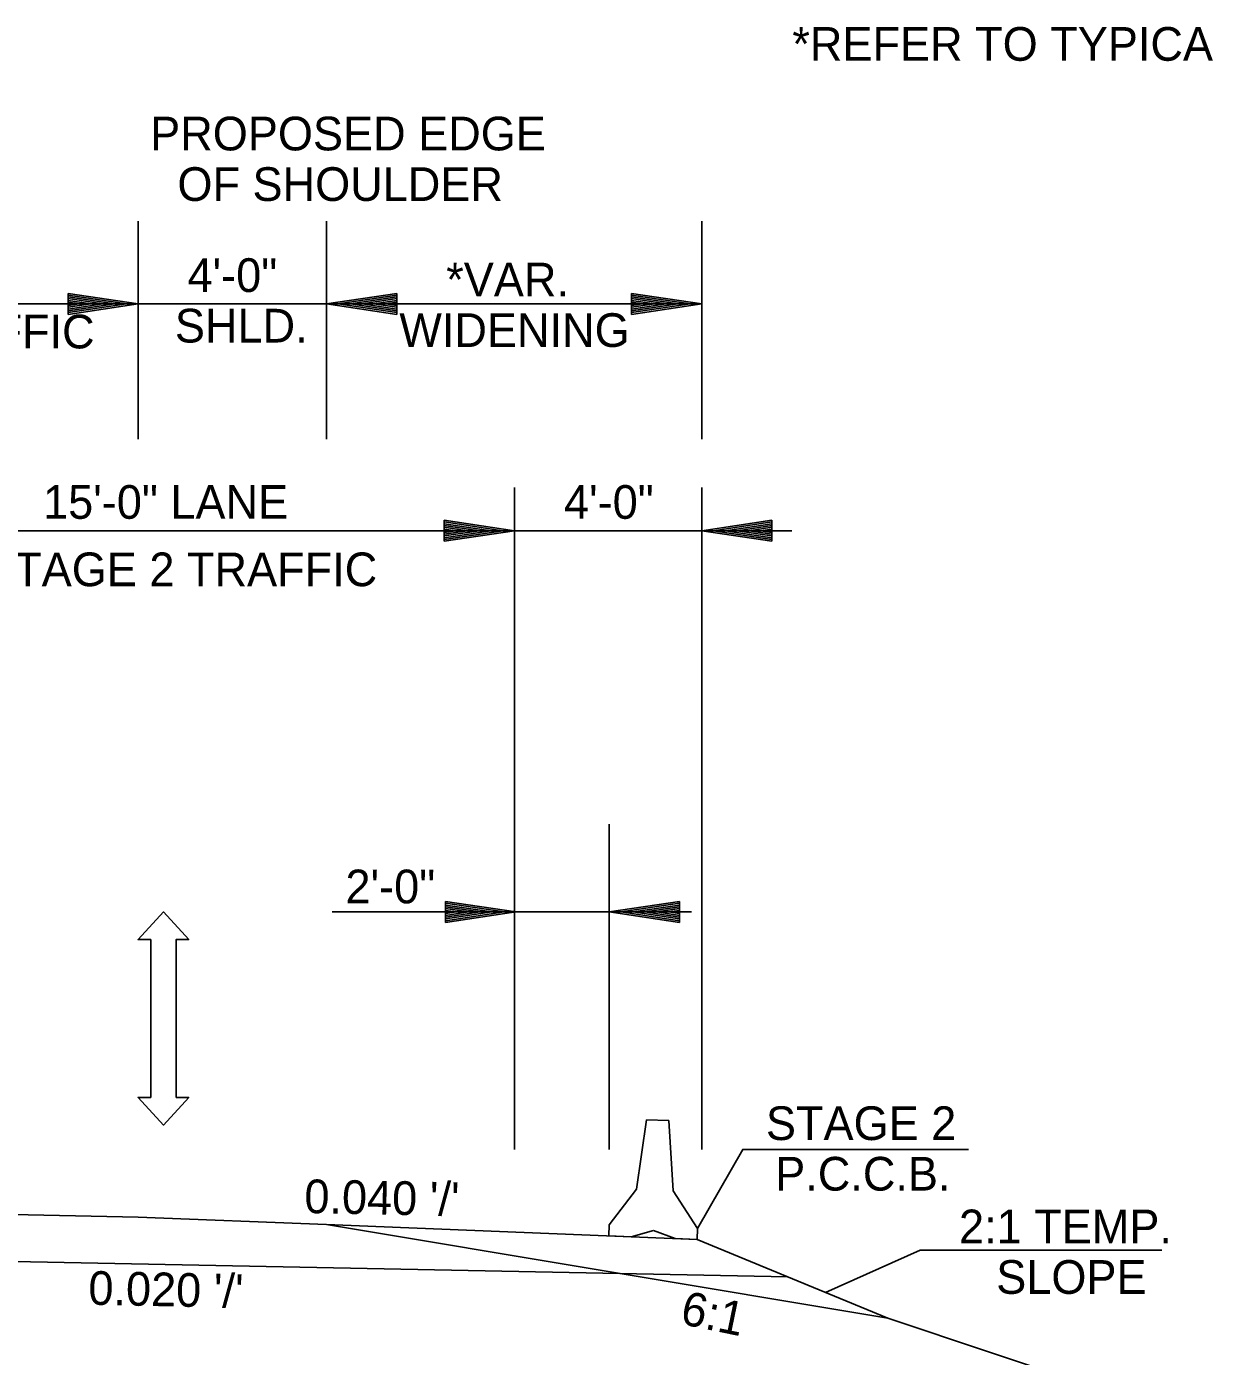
# Model space of a CAD drawing. Extents: x 1807779 to 1818251, y 673292 to 678849.
# Drawn here: x 1813573.8 to 1813826.1, y 678564.5 to 678848.6 of the extents above; entities that cross this region are included whole.
import ezdxf

# ---------------------------------------------------------------- set-up
doc = ezdxf.new("R2010")
doc.units = 0
for name, color, linetype in [('Dimensions', 7, 'Continuous'), ('EX_DRIVEWAY', 7, 'Continuous'), ('Level 1', 7, 'Continuous'), ('T_Drafting', 7, 'Continuous')]:
    doc.layers.add(name, color=color, linetype=linetype)

msp = doc.modelspace()

# ---------------------------------------------------------------- linework, layer by layer
at = {"layer": 'Dimensions'}
for p, q in [((1813597.67, 678760.42), (1813597.67, 678807.05)), ((1813637.9, 678760.42), (1813637.9, 678807.05)), ((1813718.05, 678760.42), (1813718.05, 678807.05)), ((1813582.67, 678791.59), (1813597.67, 678789.34)), ((1813582.67, 678787.09), (1813582.67, 678791.59)), ((1813582.67, 678791.22), (1813595.17, 678789.34)), ((1813582.67, 678790.84), (1813592.59, 678789.34)), ((1813582.67, 678790.46), (1813590.09, 678789.34)), ((1813582.67, 678790.08), (1813587.55, 678789.34)), ((1813582.67, 678789.7), (1813585.04, 678789.34)), ((1813652.9, 678791.59), (1813637.9, 678789.34)), ((1813652.9, 678791.22), (1813640.41, 678789.34)), ((1813652.9, 678790.84), (1813642.99, 678789.34)), ((1813652.9, 678790.46), (1813645.48, 678789.34)), ((1813652.9, 678790.08), (1813648.03, 678789.34)), ((1813652.9, 678789.7), (1813650.53, 678789.34)), ((1813652.9, 678787.09), (1813652.9, 678791.59)), ((1813703.05, 678791.59), (1813718.05, 678789.34)), ((1813703.05, 678787.09), (1813703.05, 678791.59)), ((1813703.05, 678791.22), (1813715.55, 678789.34)), ((1813703.05, 678790.84), (1813712.97, 678789.34)), ((1813703.05, 678790.46), (1813710.47, 678789.34)), ((1813703.05, 678790.08), (1813707.93, 678789.34)), ((1813703.05, 678789.7), (1813705.42, 678789.34)), ((1813487.67, 678789.34), (1813597.67, 678789.34)), ((1813582.67, 678787.09), (1813597.67, 678789.34)), ((1813582.67, 678788.62), (1813587.55, 678789.34)), ((1813582.67, 678787.85), (1813592.59, 678789.34)), ((1813582.67, 678787.47), (1813595.17, 678789.34)), ((1813582.67, 678788.23), (1813590.09, 678789.34)), ((1813582.67, 678788.99), (1813585.04, 678789.34)), ((1813597.67, 678789.34), (1813718.05, 678789.34)), ((1813652.9, 678787.09), (1813637.9, 678789.34)), ((1813652.9, 678787.47), (1813640.41, 678789.34)), ((1813652.9, 678787.85), (1813642.99, 678789.34)), ((1813652.9, 678788.23), (1813645.48, 678789.34)), ((1813652.9, 678788.62), (1813648.03, 678789.34)), ((1813652.9, 678788.99), (1813650.53, 678789.34)), ((1813703.05, 678787.09), (1813718.05, 678789.34)), ((1813703.05, 678788.62), (1813707.93, 678789.34)), ((1813703.05, 678787.85), (1813712.97, 678789.34)), ((1813703.05, 678787.47), (1813715.55, 678789.34)), ((1813703.05, 678788.23), (1813710.47, 678789.34)), ((1813703.05, 678788.99), (1813705.42, 678789.34)), ((1813678.05, 678608.69), (1813678.05, 678750.09)), ((1813718.05, 678608.69), (1813718.05, 678750.09)), ((1813663.05, 678743.12), (1813678.05, 678740.87)), ((1813663.05, 678743.12), (1813663.05, 678738.62)), ((1813663.05, 678742.75), (1813675.55, 678740.87)), ((1813663.05, 678742.37), (1813672.97, 678740.87)), ((1813663.05, 678741.99), (1813670.47, 678740.87)), ((1813663.05, 678741.6), (1813667.93, 678740.87)), ((1813663.05, 678741.23), (1813665.42, 678740.87)), ((1813733.05, 678743.12), (1813718.05, 678740.87)), ((1813733.05, 678742.75), (1813720.56, 678740.87)), ((1813733.05, 678742.37), (1813723.14, 678740.87)), ((1813733.05, 678741.99), (1813725.64, 678740.87)), ((1813733.05, 678741.61), (1813728.18, 678740.87)), ((1813733.05, 678741.23), (1813730.68, 678740.87)), ((1813733.05, 678738.62), (1813733.05, 678743.12)), ((1813528.05, 678740.87), (1813678.05, 678740.87)), ((1813663.05, 678738.62), (1813678.05, 678740.87)), ((1813663.05, 678740.14), (1813667.93, 678740.87)), ((1813663.05, 678739.38), (1813672.97, 678740.87)), ((1813663.05, 678739), (1813675.55, 678740.87)), ((1813663.05, 678739.76), (1813670.47, 678740.87)), ((1813663.05, 678740.52), (1813665.42, 678740.87)), ((1813678.05, 678740.87), (1813737.3, 678740.87)), ((1813733.05, 678738.62), (1813718.05, 678740.87)), ((1813733.05, 678739), (1813720.56, 678740.87)), ((1813733.05, 678739.38), (1813723.14, 678740.87)), ((1813733.05, 678739.76), (1813725.64, 678740.87)), ((1813733.05, 678740.15), (1813728.18, 678740.87)), ((1813733.05, 678740.52), (1813730.68, 678740.87)), ((1813698.31, 678608.69), (1813698.31, 678678.14)), ((1813663.31, 678661.66), (1813678.31, 678659.41)), ((1813663.31, 678661.66), (1813663.31, 678657.16)), ((1813713.31, 678661.66), (1813698.31, 678659.41)), ((1813713.31, 678657.16), (1813713.31, 678661.66)), ((1813715.9, 678659.41), (1813639.13, 678659.41)), ((1813663.31, 678661.28), (1813675.81, 678659.41)), ((1813663.31, 678660.9), (1813673.23, 678659.41)), ((1813663.31, 678660.53), (1813670.73, 678659.41)), ((1813663.31, 678660.14), (1813668.19, 678659.41)), ((1813663.31, 678659.76), (1813665.68, 678659.41)), ((1813663.31, 678657.16), (1813678.31, 678659.41)), ((1813663.31, 678658.67), (1813668.19, 678659.41)), ((1813663.31, 678657.92), (1813673.23, 678659.41)), ((1813663.31, 678657.53), (1813675.81, 678659.41)), ((1813663.31, 678658.29), (1813670.73, 678659.41)), ((1813663.31, 678659.06), (1813665.68, 678659.41)), ((1813713.31, 678657.16), (1813698.31, 678659.41)), ((1813713.31, 678661.28), (1813700.82, 678659.41)), ((1813713.31, 678657.53), (1813700.82, 678659.41)), ((1813713.31, 678660.9), (1813703.4, 678659.41)), ((1813713.31, 678657.92), (1813703.4, 678659.41)), ((1813713.31, 678660.53), (1813705.9, 678659.41)), ((1813713.31, 678658.29), (1813705.9, 678659.41)), ((1813713.31, 678660.14), (1813708.44, 678659.41)), ((1813713.31, 678658.68), (1813708.44, 678659.41)), ((1813713.31, 678659.76), (1813710.94, 678659.41)), ((1813713.31, 678659.06), (1813710.94, 678659.41)), ((1813600.35, 678619.79), (1813600.35, 678653.51))]:
    msp.add_line(p, q, dxfattribs=at)
for points in [[(1813605.75, 678619.79), (1813605.75, 678653.51), (1813608.45, 678653.51), (1813603.05, 678659.43), (1813597.65, 678653.51), (1813600.35, 678653.51)], [(1813600.35, 678653.51), (1813600.35, 678619.79), (1813597.65, 678619.79), (1813603.05, 678613.87), (1813608.45, 678619.79), (1813605.75, 678619.79)], [(1813717.14, 678591.79), (1813726.83, 678608.67), (1813775.05, 678608.67)], [(1813744.48, 678578.11), (1813764.72, 678587.15), (1813816.33, 678587.15)]]:
    msp.add_lwpolyline(points, dxfattribs=at)
at = {"layer": 'EX_DRIVEWAY'}
for p, q in [((1813487.67, 678596.41), (1813597.65, 678594.21)), ((1813597.65, 678594.21), (1813637.9, 678592.6)), ((1813637.9, 678592.6), (1813757.78, 678572.62)), ((1813487.67, 678586.41), (1813700.59, 678582.15)), ((1813757.78, 678572.62), (1814046.76, 678476.29))]:
    msp.add_line(p, q, dxfattribs=at)
at = {"layer": 'Level 1'}
for p, q in [((1813704.11, 678600.17), (1813706.28, 678615.02)), ((1813706.28, 678615.02), (1813710.99, 678614.83)), ((1813710.99, 678614.83), (1813711.96, 678599.86)), ((1813698.31, 678592.54), (1813704.11, 678600.17)), ((1813711.96, 678599.86), (1813717.14, 678591.79)), ((1813698.24, 678590.19), (1813698.31, 678592.54)), ((1813707.72, 678591.38), (1813702.95, 678590)), ((1813712.36, 678589.62), (1813707.72, 678591.38)), ((1813717.14, 678591.79), (1813717.07, 678589.43)), ((1813702.95, 678590), (1813698.24, 678590.19)), ((1813717.07, 678589.43), (1813712.36, 678589.62))]:
    msp.add_line(p, q, dxfattribs=at)
at = {"layer": 'T_Drafting'}
for p, q in [((1813637.9, 678592.6), (1813717.07, 678589.43)), ((1813717.07, 678589.43), (1813757.78, 678572.62)), ((1813700.59, 678582.15), (1813736.44, 678581.43))]:
    msp.add_line(p, q, dxfattribs=at)

# ---------------------------------------------------------------- texts
at = {"layer": 'Dimensions'}
for s, p in [('*REFER TO TYPICAL SECTIONS FOR WIDENING WIDTHS AND LOCATIONS.', (1813737.41, 678841.29)), ('PROPOSED EDGE ', (1813600.22, 678822.14)), ('OF SHOULDER', (1813606.04, 678811.34)), ('4\'-0" ', (1813608.19, 678791.89)), ('*VAR.', (1813663.47, 678790.94)), ('STAGE 3 TRAFFIC', (1813504.36, 678779.83)), ('SHLD. ', (1813605.5, 678781.09)), ('WIDENING', (1813653.45, 678780.14)), ('15\'-0" LANE', (1813577.34, 678743.42)), ('4\'-0"', (1813688.63, 678743.42)), ('STAGE 2 TRAFFIC', (1813564.74, 678729.02)), ('2\'-0"', (1813641.94, 678661.26)), ('STAGE 2', (1813731.77, 678610.68)), ('P.C.C.B.', (1813733.75, 678599.88)), ('2:1 TEMP. ', (1813773.02, 678588.62)), ('SLOPE', (1813780.97, 678577.82))]:
    msp.add_text(s, height=7.2, dxfattribs=at).set_placement(p)
for s, rotation, p in [("0.040 '/'", 358.8777, (1813633.11, 678595.09)), ("0.020 '/'", 358.7593, (1813586.96, 678575.51)), ('6:1', 348.3502, (1813713.22, 678571.45))]:
    msp.add_text(s, height=7.2, rotation=rotation, dxfattribs=at).set_placement(p)

doc.saveas('drawing.dxf')
